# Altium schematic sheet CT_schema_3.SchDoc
size 278 x 192 mm
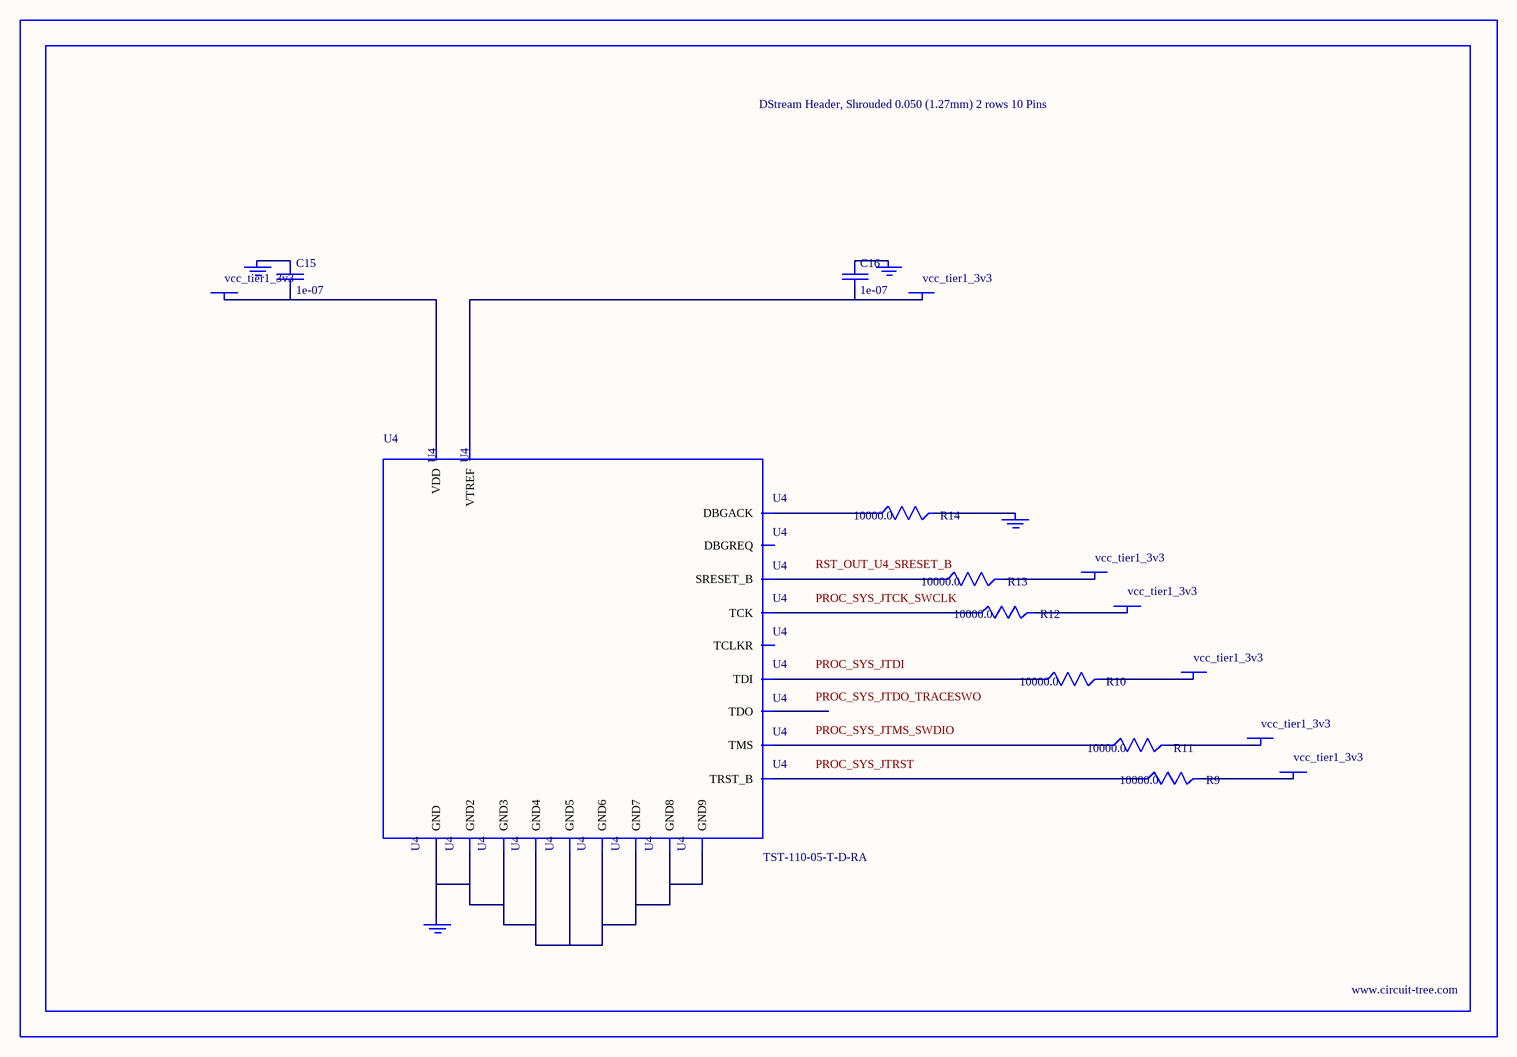
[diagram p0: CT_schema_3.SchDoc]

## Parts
BORDER2  (no value)
C15  1e-07  [C0402]
C16  1e-07  [C0402]
GND_INSTANCE_2_0  (no value)
GND_INSTANCE_2_1  (no value)
GND_INSTANCE_2_2  (no value)
GND_INSTANCE_2_3  (no value)
POWER_INSTANCE_2_0  vcc_tier1_3v3
POWER_INSTANCE_2_1  vcc_tier1_3v3
POWER_INSTANCE_2_2  vcc_tier1_3v3
POWER_INSTANCE_2_3  vcc_tier1_3v3
POWER_INSTANCE_2_4  vcc_tier1_3v3
POWER_INSTANCE_2_5  vcc_tier1_3v3
POWER_INSTANCE_2_6  vcc_tier1_3v3
R9  10000.0  [R0603]
R10  10000.0  [R0603]
R11  10000.0  [R0603]
R12  10000.0  [R0603]
R13  10000.0  [R0603]
R14  10000.0  [R0603]
U4  TST-110-05-T-D-RA  [TST-110-05-T-D-RA]

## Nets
NetC15_1: C15.1 GND_INSTANCE_2_1.0(GND)
NetC15_2: C15.2 POWER_INSTANCE_2_1.0(PWR) U4.2(VDD)
NetC16_1: C16.1 GND_INSTANCE_2_0.0(GND)
NetC16_2: C16.2 POWER_INSTANCE_2_0.0(PWR) U4.1(VTREF)
NetGND_INSTANCE_2_2_0: GND_INSTANCE_2_2.0(GND) R14.2
NetGND_INSTANCE_2_3_0: GND_INSTANCE_2_3.0(GND) U4.4(GND) U4.6(GND2) U4.8(GND3) U4.10(GND4) U4.12(GND5) U4.14(GND6) U4.16(GND7) U4.18(GND8) U4.20(GND9)
NetPOWER_INSTANCE_2_2_0: POWER_INSTANCE_2_2.0(PWR) R9.2
NetPOWER_INSTANCE_2_3_0: POWER_INSTANCE_2_3.0(PWR) R10.2
NetPOWER_INSTANCE_2_4_0: POWER_INSTANCE_2_4.0(PWR) R11.2
NetPOWER_INSTANCE_2_5_0: POWER_INSTANCE_2_5.0(PWR) R12.2
NetPOWER_INSTANCE_2_6_0: POWER_INSTANCE_2_6.0(PWR) R13.2
NetR9_1: R9.1 U4.3(TRST_B)
NetR10_1: R10.1 U4.5(TDI)
NetR11_1: R11.1 U4.7(TMS)
NetR12_1: R12.1 U4.9(TCK)
NetR13_1: R13.1 U4.15(SRESET_B)
NetR14_1: R14.1 U4.19(DBGACK)

Not connected (* = marked no-connect by the designer): U4 11(TCLKR) 13(TDO) 17(DBGREQ)

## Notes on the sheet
- Labels drawn without touching a wire or pin: PROC_SYS_JTCK_SWCLK, PROC_SYS_JTDI, PROC_SYS_JTDO_TRACESWO, PROC_SYS_JTMS_SWDIO, PROC_SYS_JTRST, RST_OUT_U4_SRESET_B

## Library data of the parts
BORDER2 = BORDER_PAGE2
C15 C16 = C0402C104K3RACTU
GND_INSTANCE_2_0-GND_INSTANCE_2_3 = GND
POWER_INSTANCE_2_0-POWER_INSTANCE_2_6 = PWR
R9-R14 = RC0603JR-0710KL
